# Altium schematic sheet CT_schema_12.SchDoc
size 519 x 434 mm
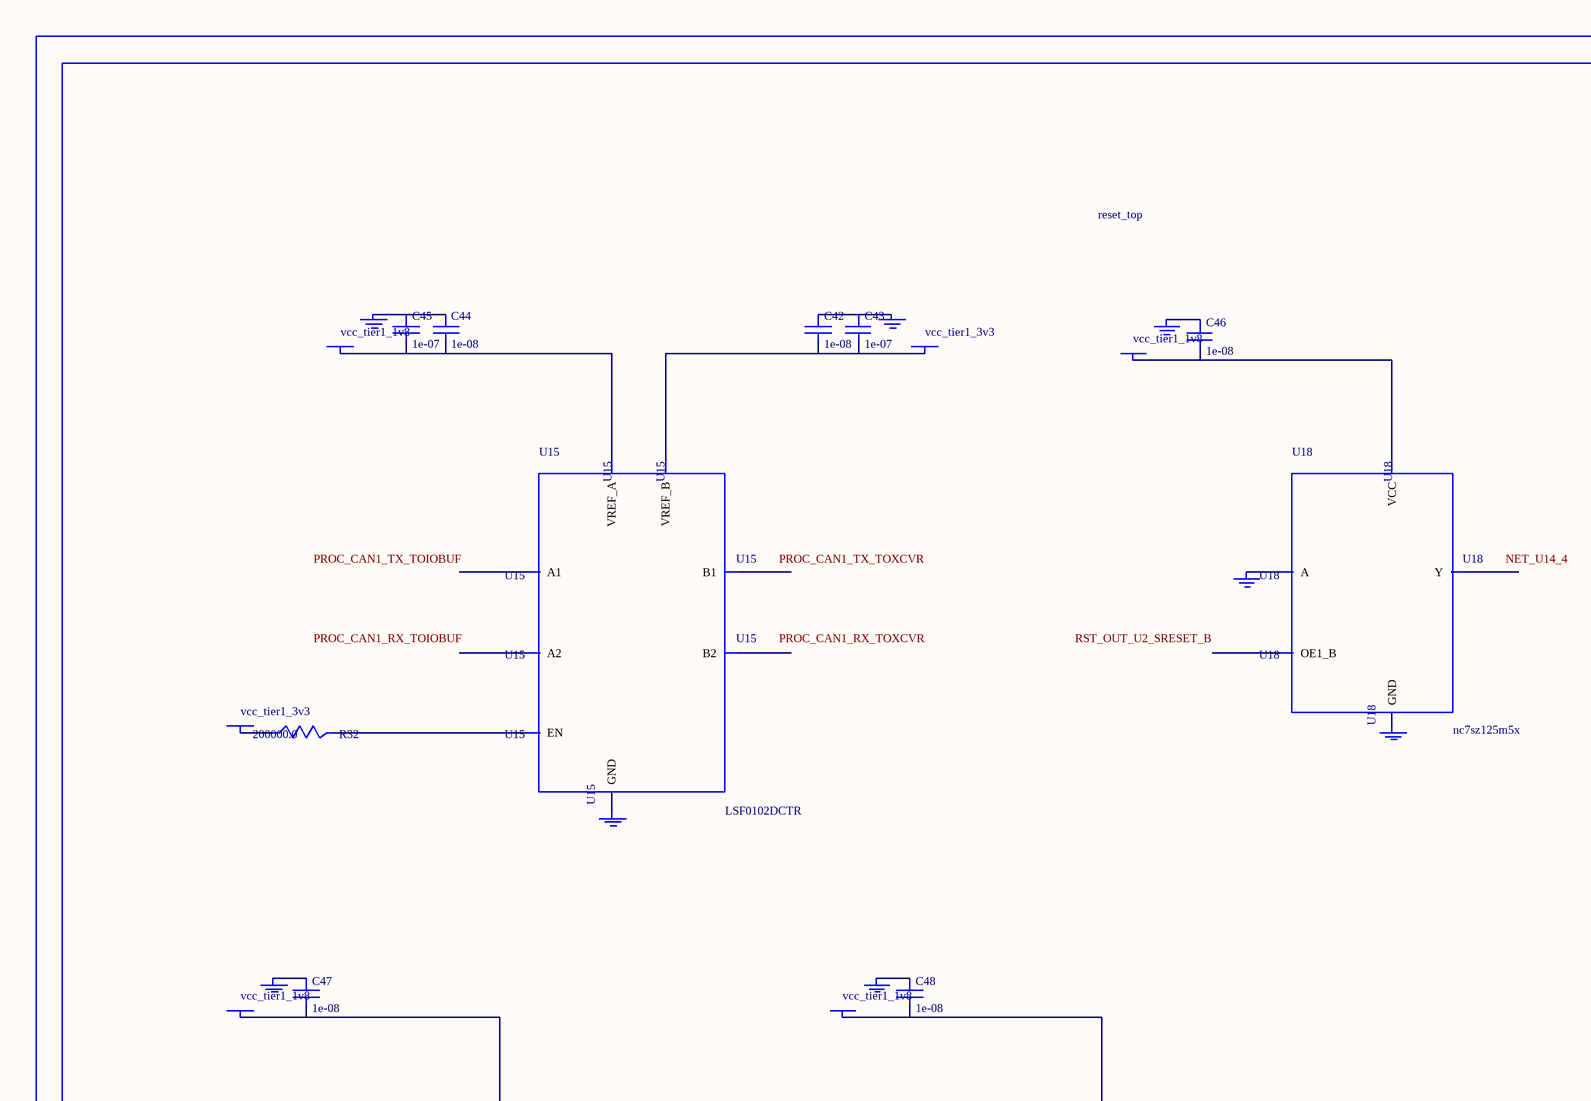
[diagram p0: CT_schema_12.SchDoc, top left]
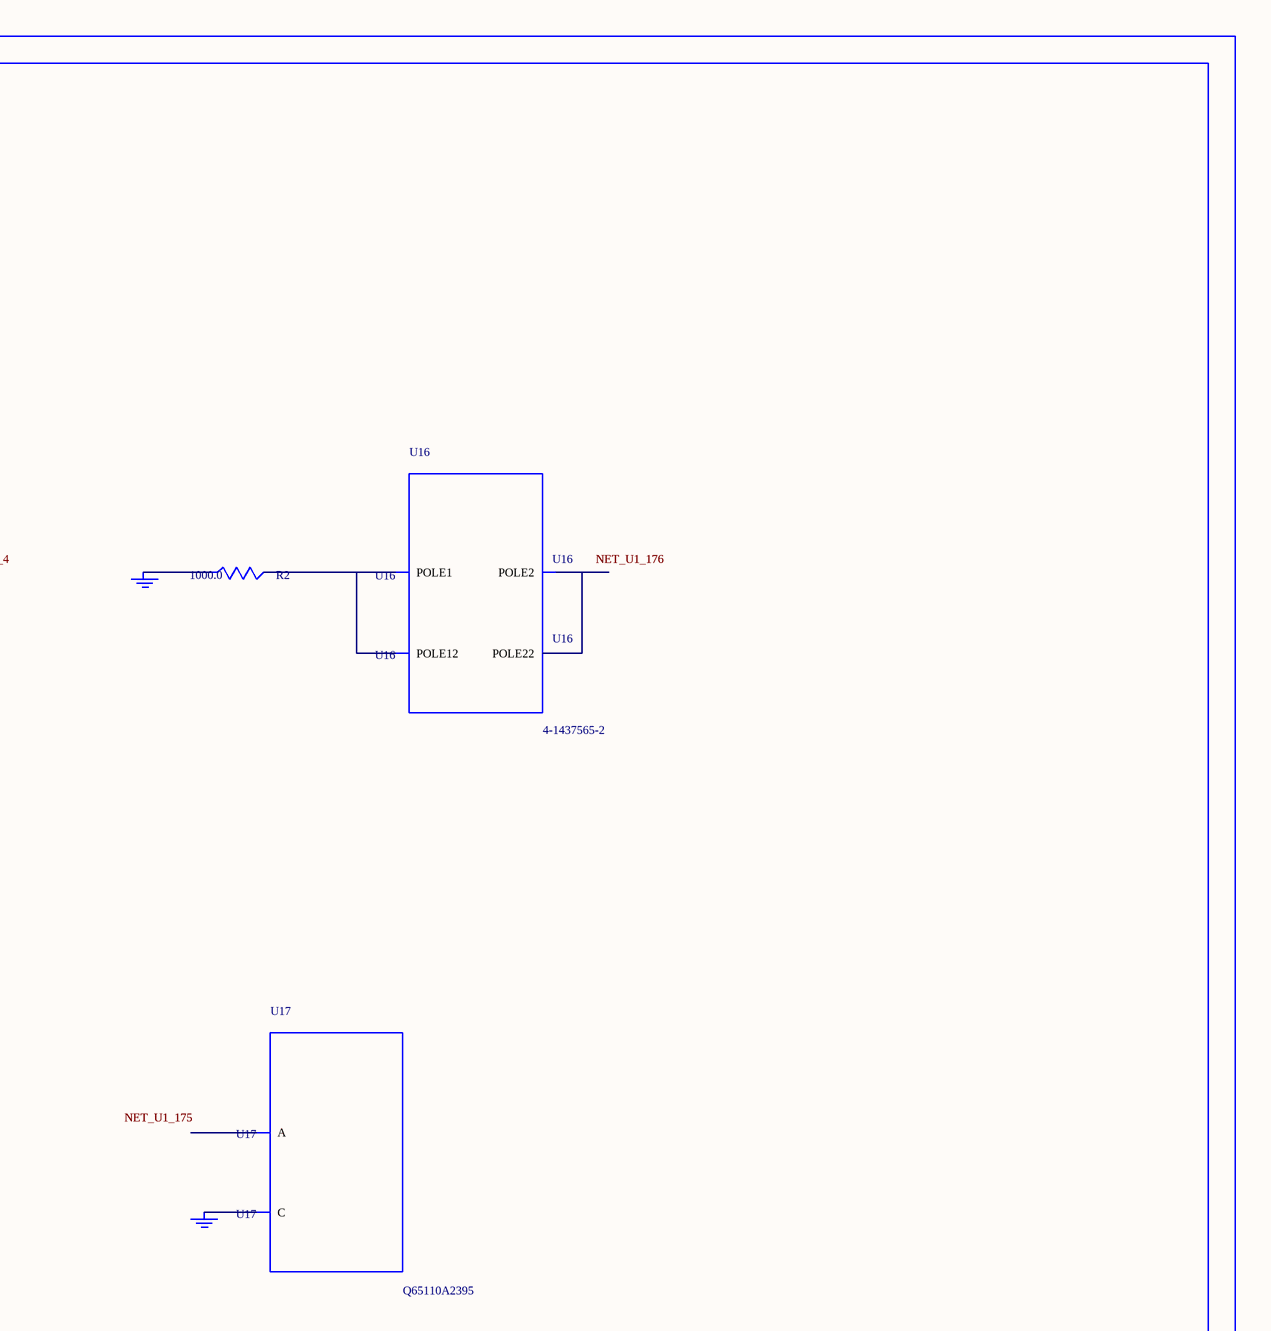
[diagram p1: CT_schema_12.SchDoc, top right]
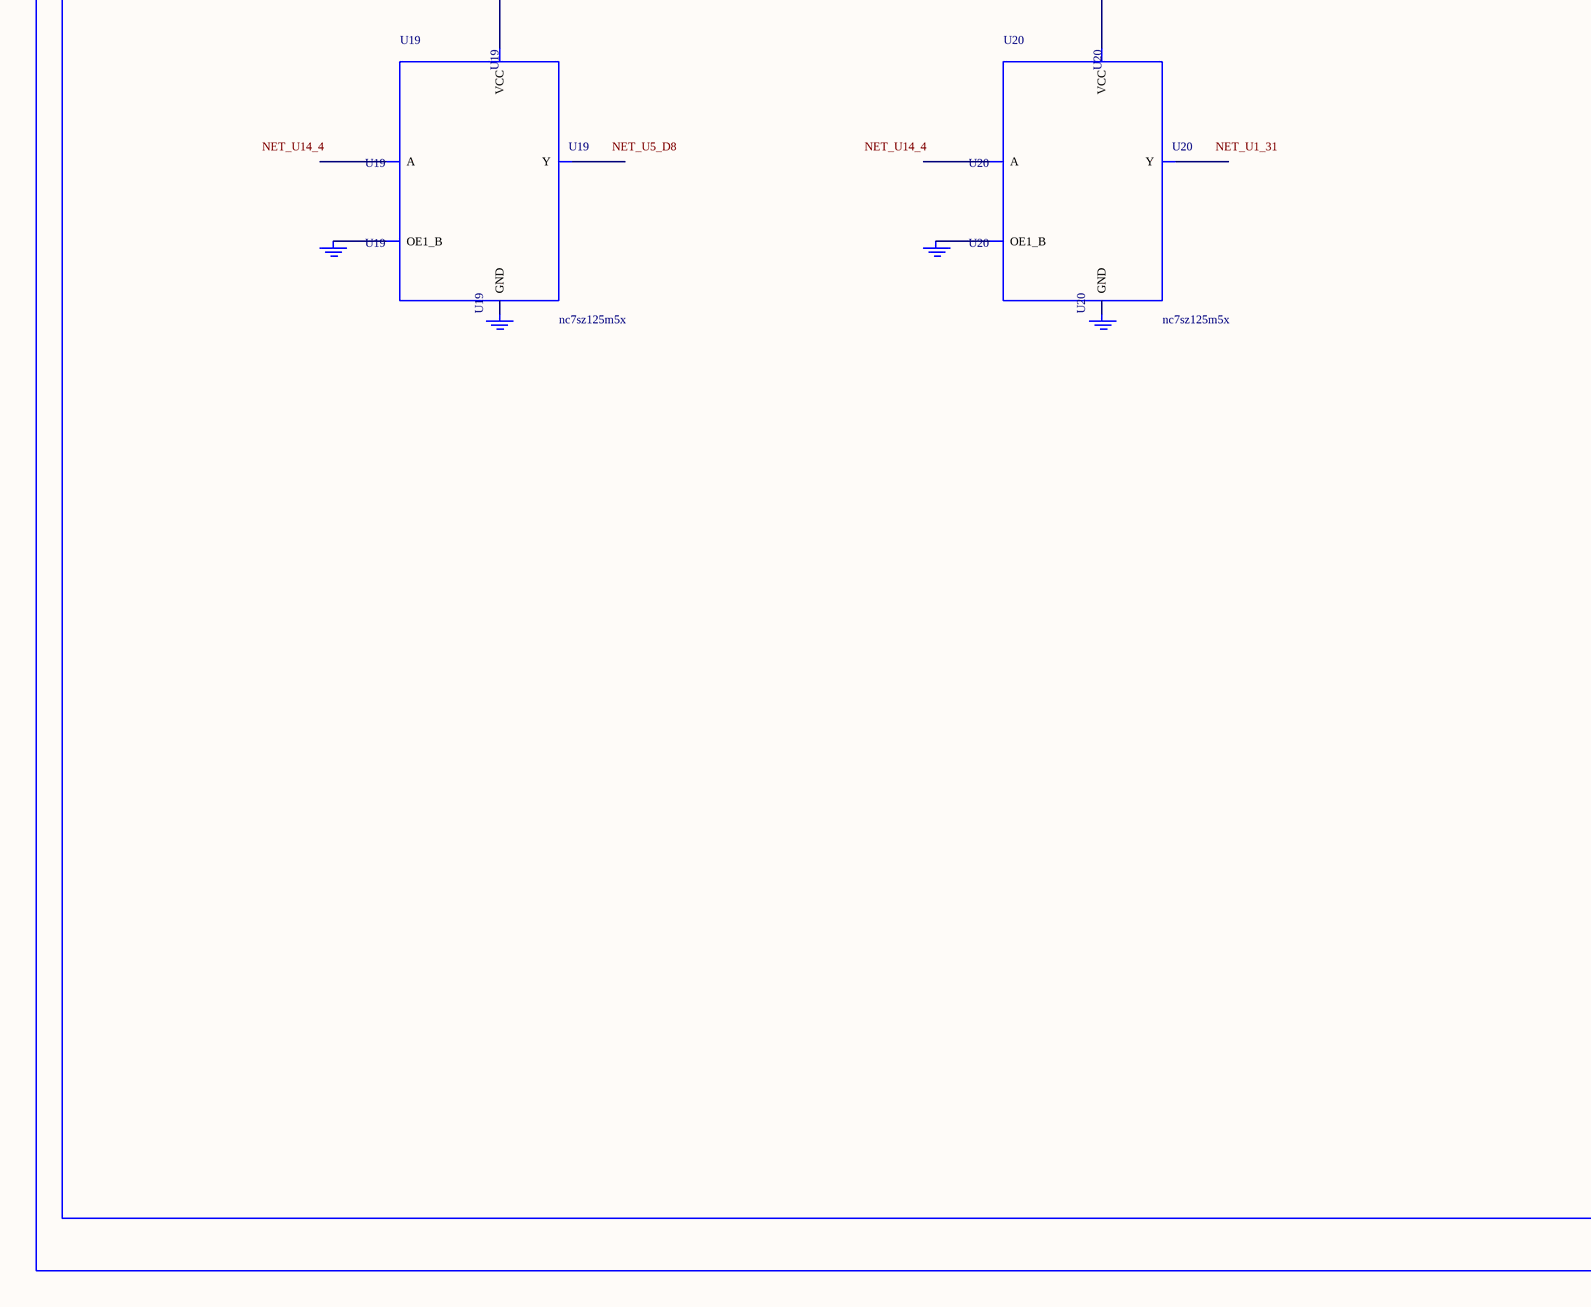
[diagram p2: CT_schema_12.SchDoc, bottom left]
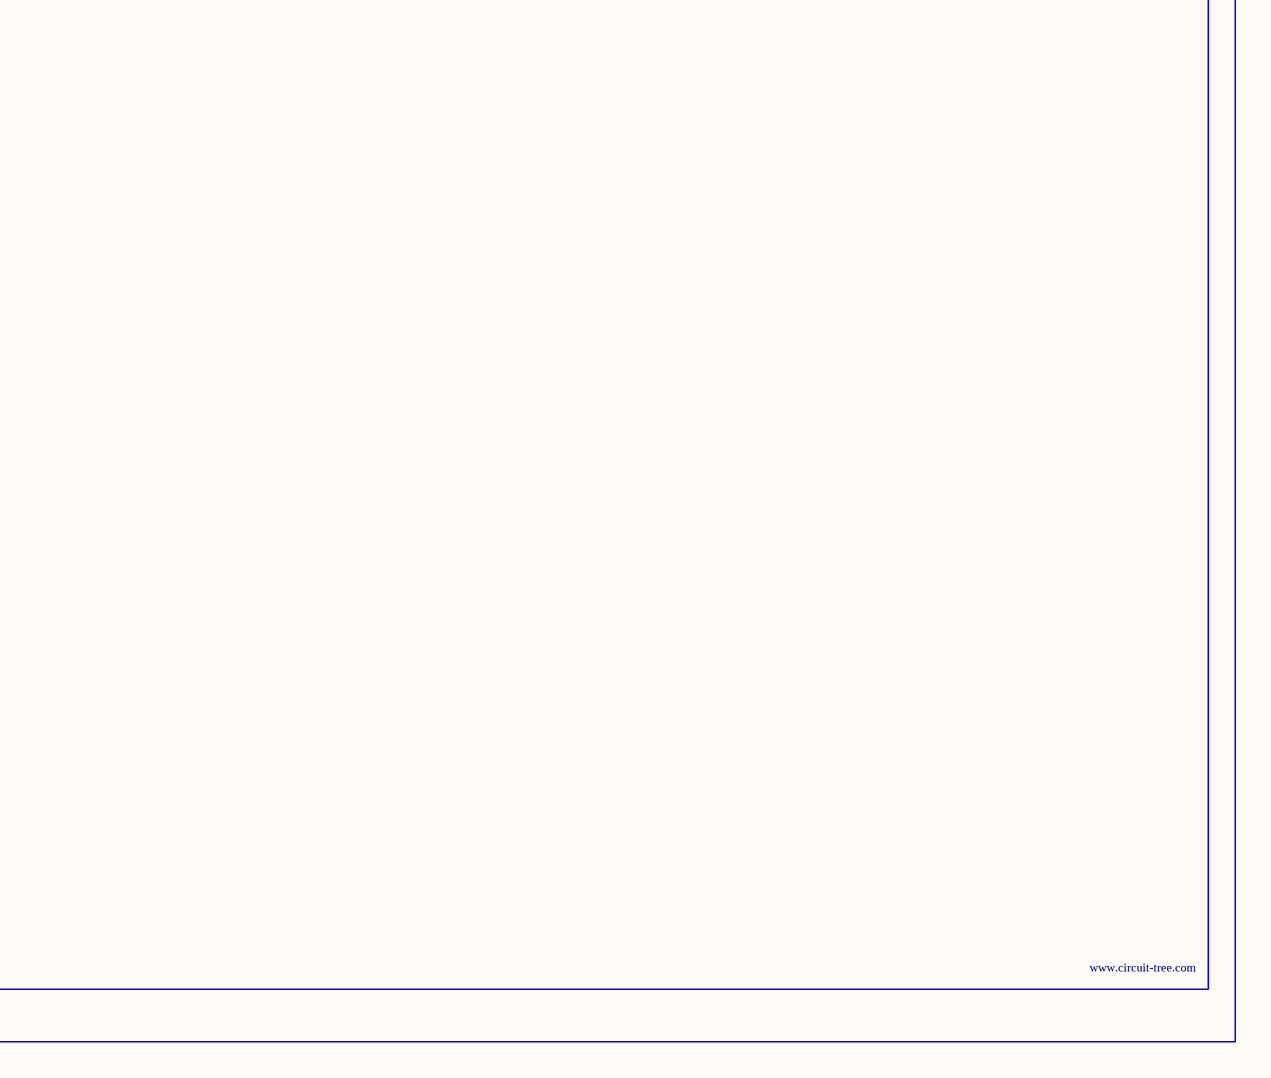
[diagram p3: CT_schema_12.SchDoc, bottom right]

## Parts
BORDER11  (no value)
C42  1e-08  [C0402]
C43  1e-07  [C0402]
C44  1e-08  [C0402]
C45  1e-07  [C0402]
C46  1e-08  [C0402]
C47  1e-08  [C0402]
C48  1e-08  [C0402]
GND_INSTANCE_11_0  (no value)
GND_INSTANCE_11_1  (no value)
GND_INSTANCE_11_2  (no value)
GND_INSTANCE_11_3  (no value)
GND_INSTANCE_11_4  (no value)
GND_INSTANCE_11_5  (no value)
GND_INSTANCE_11_6  (no value)
GND_INSTANCE_11_7  (no value)
GND_INSTANCE_11_8  (no value)
GND_INSTANCE_11_9  (no value)
GND_INSTANCE_11_10  (no value)
GND_INSTANCE_11_11  (no value)
GND_INSTANCE_11_12  (no value)
GND_INSTANCE_11_13  (no value)
POWER_INSTANCE_11_0  vcc_tier1_1v8
POWER_INSTANCE_11_1  vcc_tier1_3v3
POWER_INSTANCE_11_2  vcc_tier1_3v3
POWER_INSTANCE_11_3  vcc_tier1_1v8
POWER_INSTANCE_11_4  vcc_tier1_1v8
POWER_INSTANCE_11_5  vcc_tier1_1v8
R2  1000.0  [R0603]
R32  200000.0  [R0603]
U15  LSF0102DCTR  [DCU0008A_N]
U16  4-1437565-2  [SW_4-1437565-2]
U17  Q65110A2395  [LGM67K-G1J2-24-Z]
U18  nc7sz125m5x  [NC7SZ125M5X]
U19  nc7sz125m5x  [NC7SZ125M5X]
U20  nc7sz125m5x  [NC7SZ125M5X]

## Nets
NetC42_1: C42.1 C43.1 GND_INSTANCE_11_1.0(GND)
NetC42_2: C42.2 C43.2 POWER_INSTANCE_11_1.0(PWR) U15.7(VREF_B)
NetC44_1: C44.1 C45.1 GND_INSTANCE_11_0.0(GND)
NetC44_2: C44.2 C45.2 POWER_INSTANCE_11_0.0(PWR) U15.2(VREF_A)
NetC46_1: C46.1 GND_INSTANCE_11_5.0(GND)
NetC46_2: C46.2 POWER_INSTANCE_11_3.0(PWR) U18.5(VCC)
NetC47_1: C47.1 GND_INSTANCE_11_8.0(GND)
NetC47_2: C47.2 POWER_INSTANCE_11_4.0(PWR) U19.5(VCC)
NetC48_1: C48.1 GND_INSTANCE_11_11.0(GND)
NetC48_2: C48.2 POWER_INSTANCE_11_5.0(PWR) U20.5(VCC)
NetGND_INSTANCE_11_2_0: GND_INSTANCE_11_2.0(GND) U15.1(GND)
NetGND_INSTANCE_11_3_0: GND_INSTANCE_11_3.0(GND) R2.1
NetGND_INSTANCE_11_4_0: GND_INSTANCE_11_4.0(GND) U17.C
NetGND_INSTANCE_11_6_0: GND_INSTANCE_11_6.0(GND) U18.2(A)
NetGND_INSTANCE_11_7_0: GND_INSTANCE_11_7.0(GND) U18.3(GND)
NetGND_INSTANCE_11_9_0: GND_INSTANCE_11_9.0(GND) U19.1(OE1_B)
NetGND_INSTANCE_11_10_0: GND_INSTANCE_11_10.0(GND) U19.3(GND)
NetGND_INSTANCE_11_12_0: GND_INSTANCE_11_12.0(GND) U20.1(OE1_B)
NetGND_INSTANCE_11_13_0: GND_INSTANCE_11_13.0(GND) U20.3(GND)
NetPOWER_INSTANCE_11_2_0: POWER_INSTANCE_11_2.0(PWR) R32.1
NetR2_2: R2.2 U16.1(POLE1) U16.2(POLE12)
NetR32_2: R32.2 U15.8(EN)
NetU16_3: U16.3(POLE2) U16.4(POLE22)

Not connected (* = marked no-connect by the designer): U15 3(A1) 4(A2) 5(B2) 6(B1); U17 A; U18 1(OE1_B) 4(Y); U19 2(A) 4(Y); U20 2(A) 4(Y)

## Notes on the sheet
- Labels drawn without touching a wire or pin: NET_U1_31, NET_U5_D8, NET_U14_4, PROC_CAN1_RX_TOIOBUF, PROC_CAN1_RX_TOXCVR, PROC_CAN1_TX_TOIOBUF, PROC_CAN1_TX_TOXCVR, RST_OUT_U2_SRESET_B

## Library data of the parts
BORDER11 = BORDER_PAGE11
C42 C44 C46-C48 = C0402C103K3RAC
C43 C45 = C0402C104K3RACTU
GND_INSTANCE_11_0-GND_INSTANCE_11_13 = GND
POWER_INSTANCE_11_0-POWER_INSTANCE_11_5 = PWR
R2 = RC0603JR-071KL
R32 = RC0603JR-07200KL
